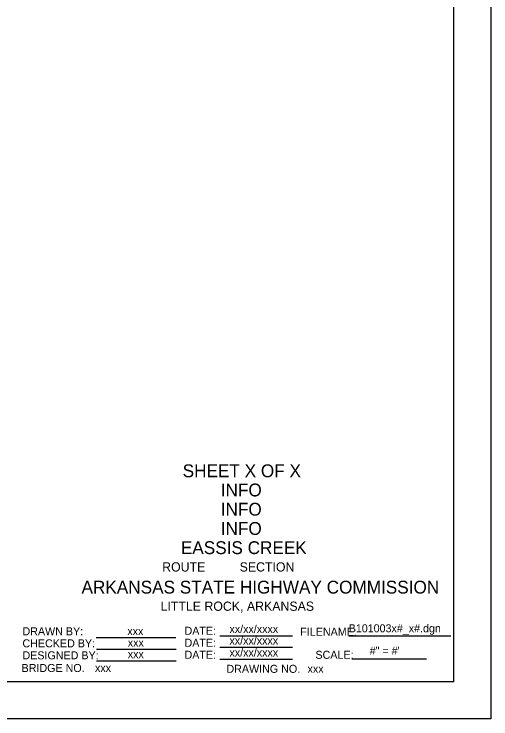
# Model space of a CAD drawing. Extents: x 16 to 1228740, y 11 to 152440.
# Drawn here: x 17.87 to 18.49, y 10.709 to 11.626 of the extents above; entities that cross this region are included whole.
import ezdxf

# ---------------------------------------------------------------- set-up
doc = ezdxf.new("R2010")
doc.units = 0
for name, color, linetype in [('B_Copy In', 7, 'Continuous'), ('B_County and Route', 7, 'Continuous'), ('B_Text', 7, 'Continuous'), ('B_Title Text', 7, 'Continuous'), ('R_Border', 7, 'Continuous')]:
    doc.layers.add(name, color=color, linetype=linetype)

msp = doc.modelspace()

# ---------------------------------------------------------------- linework, layer by layer
at = {"layer": 'B_Text'}
for p, q in [((18.13771, 10.81765), (18.23221, 10.81765)), ((18.30529, 10.81765), (18.43835, 10.81765)), ((17.97661, 10.81515), (18.08021, 10.81515)), ((17.97721, 10.80015), (18.08081, 10.80015)), ((18.13771, 10.80265), (18.23221, 10.80265)), ((18.13771, 10.80265), (18.23221, 10.80265)), ((17.97721, 10.78515), (18.08081, 10.78515)), ((18.13771, 10.78703), (18.23221, 10.78703)), ((18.30917, 10.78765), (18.40631, 10.78765))]:
    msp.add_line(p, q, dxfattribs=at)
at = {"layer": 'R_Border'}
for q in [(18.44221, 12.49475), (15.78327, 10.75755)]:
    msp.add_line((18.44221, 10.75755), q, dxfattribs=at)
msp.add_lwpolyline([(15.65694, 12.54282), (18.49027, 12.54282), (18.49027, 10.70949), (15.65694, 10.70949)], close=True, dxfattribs=at)

# ---------------------------------------------------------------- texts
at = {"layer": 'B_Copy In'}
for s, height, p in [('SHEET X OF X', 0.0167, (18.08929, 11.02383)), ('INFO', 0.0167, (18.13883, 10.99888)), ('INFO', 0.0167, (18.13883, 10.97383)), ('INFO', 0.0167, (18.13883, 10.94878)), ('xxx', 0.0104, (18.0173, 10.81846)), ('xx/xx/xxxx', 0.0104, (18.15019, 10.82119)), ('B101003x#_x#.dgn', 0.0104, (18.30529, 10.8221)), ('xx/xx/xxxx', 0.0104, (18.15019, 10.80619)), ('xxx', 0.0104, (18.0179, 10.80346)), ('xx/xx/xxxx', 0.0104, (18.15019, 10.79057)), ('#" = #\'', 0.0104, (18.33262, 10.79302)), ('xxx', 0.0104, (18.0179, 10.78846)), ('xxx', 0.010417, (17.97523, 10.7706)), ('xxx', 0.010417, (18.25173, 10.76944))]:
    msp.add_text(s, height=height, dxfattribs=at).set_placement(p)
at = {"layer": 'B_County and Route'}
msp.add_text('EASSIS CREEK', height=0.0167, dxfattribs=at).set_placement((18.08696, 10.92383))
at = {"layer": 'B_Text'}
for s, height, p in [('DRAWN BY:', 0.010417, (17.88091, 10.8182)), ('DATE:', 0.010417, (18.09171, 10.8189)), ('FILENAME:', 0.010417, (18.24229, 10.81765)), ('CHECKED BY:', 0.0104166, (17.88091, 10.80257)), ('DATE:', 0.010417, (18.09171, 10.80328)), ('DESIGNED BY:', 0.0104166, (17.88091, 10.78695)), ('DATE:', 0.010417, (18.09171, 10.78765)), ('SCALE:', 0.010417, (18.26201, 10.78765)), ('BRIDGE NO.', 0.010417, (17.87978, 10.77048)), ('DRAWING NO.', 0.0104166, (18.14623, 10.76942))]:
    msp.add_text(s, height=height, dxfattribs=at).set_placement(p)
at = {"layer": 'B_Title Text'}
for s, height, p in [('ROUTE          SECTION ', 0.012, (18.06263, 10.90115)), ('ARKANSAS STATE HIGHWAY COMMISSION', 0.0167, (17.95772, 10.8725)), ('LITTLE ROCK, ARKANSAS', 0.012, (18.0605, 10.85007))]:
    msp.add_text(s, height=height, dxfattribs=at).set_placement(p)

doc.saveas('drawing.dxf')
